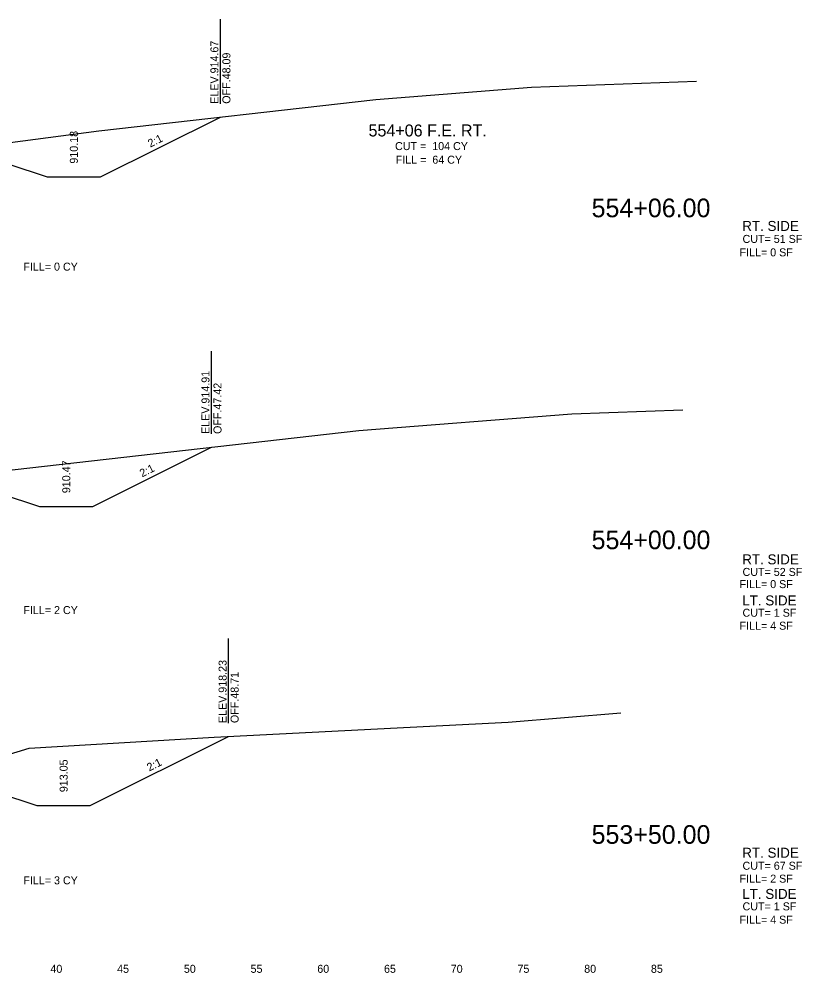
# Model space of a CAD drawing. Extents: x -4 to 359, y 0 to 1436.
# Drawn here: x 285.5 to 344.2, y 1200.5 to 1272 of the extents above; entities that cross this region are included whole.
import ezdxf

# ---------------------------------------------------------------- set-up
doc = ezdxf.new("R2010")
doc.units = 0
for name, color, linetype in [('XS-Existing surface-ground', 7, 'Continuous'), ('XS-Proposed surface-ground', 7, 'Continuous'), ('XS-Text-ditch slope', 7, 'Continuous'), ('XS-Text-earthwork labels', 7, 'Continuous'), ('XS-Text-offset label', 7, 'Continuous'), ('XS-Text-profile report', 7, 'Continuous'), ('XS-Text-tie elevation', 7, 'Continuous'), ('XS-Text-tie offset', 7, 'Continuous')]:
    doc.layers.add(name, color=color, linetype=linetype)

msp = doc.modelspace()

# ---------------------------------------------------------------- linework, layer by layer
at = {"layer": 'XS-Existing surface-ground'}
for p, q in [((312.25, 1265.962), (323.913, 1266.872)), ((323.913, 1266.872), (336.277, 1267.323)), ((291.485, 1263.596), (312.25, 1265.962)), ((283.172, 1262.511), (291.485, 1263.596)), ((326.923, 1242.377), (335.247, 1242.681)), ((310.956, 1241.132), (326.923, 1242.377)), ((282.746, 1237.917), (310.956, 1241.132)), ((322.167, 1219.258), (330.6, 1219.967)), ((300.127, 1218.137), (322.167, 1219.258)), ((286.257, 1217.301), (300.127, 1218.137)), ((275.709, 1214.167), (286.257, 1217.301))]:
    msp.add_line(p, q, dxfattribs=at)
at = {"layer": 'XS-Proposed surface-ground'}
for points in [[(281.609, 1262.123), (287.609, 1260.143), (291.609, 1260.143), (300.591, 1264.634)], [(281.041, 1237.413), (287.041, 1235.433), (291.041, 1235.433), (299.923, 1239.874)], [(280.844, 1214.991), (286.844, 1213.011), (290.844, 1213.011), (301.206, 1218.192)]]:
    msp.add_lwpolyline(points, dxfattribs=at)
at = {"layer": 'XS-Text-tie offset'}
for p, q in [((300.591, 1265.634), (300.591, 1271.984)), ((299.923, 1240.874), (299.923, 1247.074)), ((301.206, 1219.192), (301.206, 1225.542))]:
    msp.add_line(p, q, dxfattribs=at)

# ---------------------------------------------------------------- texts
at = {"layer": 'XS-Text-ditch slope'}
for p in [(295.34, 1262.343), (294.722, 1237.609), (295.265, 1215.557)]:
    msp.add_text('2:1', height=0.6, rotation=26.56505, dxfattribs=at).set_placement(p)
at = {"layer": 'XS-Text-earthwork labels'}
for s, height, p in [('554+06 F.E. RT.', 0.9, (311.692, 1263.182)), ('CUT =  104 CY           ', 0.6, (313.678, 1262.16)), ('FILL =  64 CY           ', 0.6, (313.729, 1261.138)), ('RT. SIDE', 0.75, (339.696, 1256.096)), (' CUT= 51 SF           ', 0.6, (339.495, 1255.198)), ('FILL= 0 SF           ', 0.6, (339.495, 1254.19)), ('FILL= 0 CY           ', 0.6, (285.826, 1253.118)), ('RT. SIDE', 0.75, (339.696, 1231.094)), (' CUT= 52 SF           ', 0.6, (339.495, 1230.226)), ('FILL= 0 SF           ', 0.6, (339.495, 1229.312)), ('LT. SIDE', 0.75, (339.696, 1228.013)), ('FILL= 2 CY           ', 0.6, (285.826, 1227.366)), (' CUT= 1 SF           ', 0.6, (339.495, 1227.166)), ('FILL= 4 SF           ', 0.6, (339.495, 1226.191)), ('RT. SIDE', 0.75, (339.696, 1209.094)), (' CUT= 67 SF           ', 0.6, (339.495, 1208.193)), ('FILL= 3 CY           ', 0.6, (285.826, 1207.099)), ('FILL= 2 SF           ', 0.6, (339.495, 1207.226)), ('LT. SIDE', 0.75, (339.696, 1206.005)), (' CUT= 1 SF           ', 0.6, (339.495, 1205.148)), ('FILL= 4 SF           ', 0.6, (339.495, 1204.151))]:
    msp.add_text(s, height=height, dxfattribs=at).set_placement(p)
at = {"layer": 'XS-Text-offset label'}
for s, height, p in [('           554+06.00           ', 1.4, (322.687, 1257.123)), ('           554+00.00           ', 1.4, (322.687, 1232.231)), ('           553+50.00           ', 1.4, (322.687, 1210.138)), ('           40           ', 0.6, (285.4, 1200.464)), ('           45           ', 0.6, (290.4, 1200.464)), ('           50           ', 0.6, (295.4, 1200.464)), ('           55           ', 0.6, (300.4, 1200.464)), ('           60           ', 0.6, (305.4, 1200.464)), ('           65           ', 0.6, (310.4, 1200.464)), ('           70           ', 0.6, (315.4, 1200.464)), ('           75           ', 0.6, (320.4, 1200.464)), ('           80           ', 0.6, (325.4, 1200.464)), ('           85           ', 0.6, (330.4, 1200.464))]:
    msp.add_text(s, height=height, dxfattribs=at).set_placement(p)
at = {"layer": 'XS-Text-profile report'}
for s, p in [('Dtch_Bkslp_1_T', (300.58, 1264.633)), ('Dtch_Frslp_1_B', (287.597, 1260.142)), ('Dtch_Bkslp_1_B', (291.597, 1260.142)), ('Dtch_Bkslp_1_T', (299.911, 1239.873)), ('Dtch_Frslp_1_B', (287.03, 1235.433)), ('Dtch_Bkslp_1_B', (291.03, 1235.433)), ('Dtch_Bkslp_1_T', (301.195, 1218.191)), ('Dtch_Frslp_1_B', (286.832, 1213.01)), ('Dtch_Bkslp_1_B', (290.832, 1213.01))]:
    msp.add_text(s, height=0.00167, dxfattribs=at).set_placement(p)
at = {"layer": 'XS-Text-tie elevation'}
for s, p in [('ELEV.914.67', (300.441, 1265.634)), ('OFF.48.09', (301.341, 1265.634)), ('910.18', (289.909, 1261.143)), ('ELEV.914.91', (299.773, 1240.874)), ('OFF.47.42', (300.673, 1240.874)), ('910.47', (289.341, 1236.433)), ('ELEV.918.23', (301.056, 1219.192)), ('OFF.48.71', (301.956, 1219.192)), ('913.05', (289.144, 1214.011))]:
    msp.add_text(s, height=0.6, rotation=90, dxfattribs=at).set_placement(p)

doc.saveas('drawing.dxf')
